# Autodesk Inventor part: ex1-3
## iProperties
Author: Administrator
Created: 2001-03
Part Number: ex1-3
Document SubType Name: Modeling
Designer: Administrator
Control State: 0
Master: False
Checked Out: False
PropertySet Name: Design Tracking Control
Shininess: 5.0
PropertySet Name: _Private Model Information
Density: 0.0
Volumn: 0.0
Area: 0.0
PropertySet Name: Model Information
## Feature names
1. Extrusion1
2. Extrusion2
3. Hole1
4. Fillet1
5. Loft1
6. Mirror1
7. Sweep1
8. Fillet2
